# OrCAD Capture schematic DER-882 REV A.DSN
size C; title: DER 882; rev: A
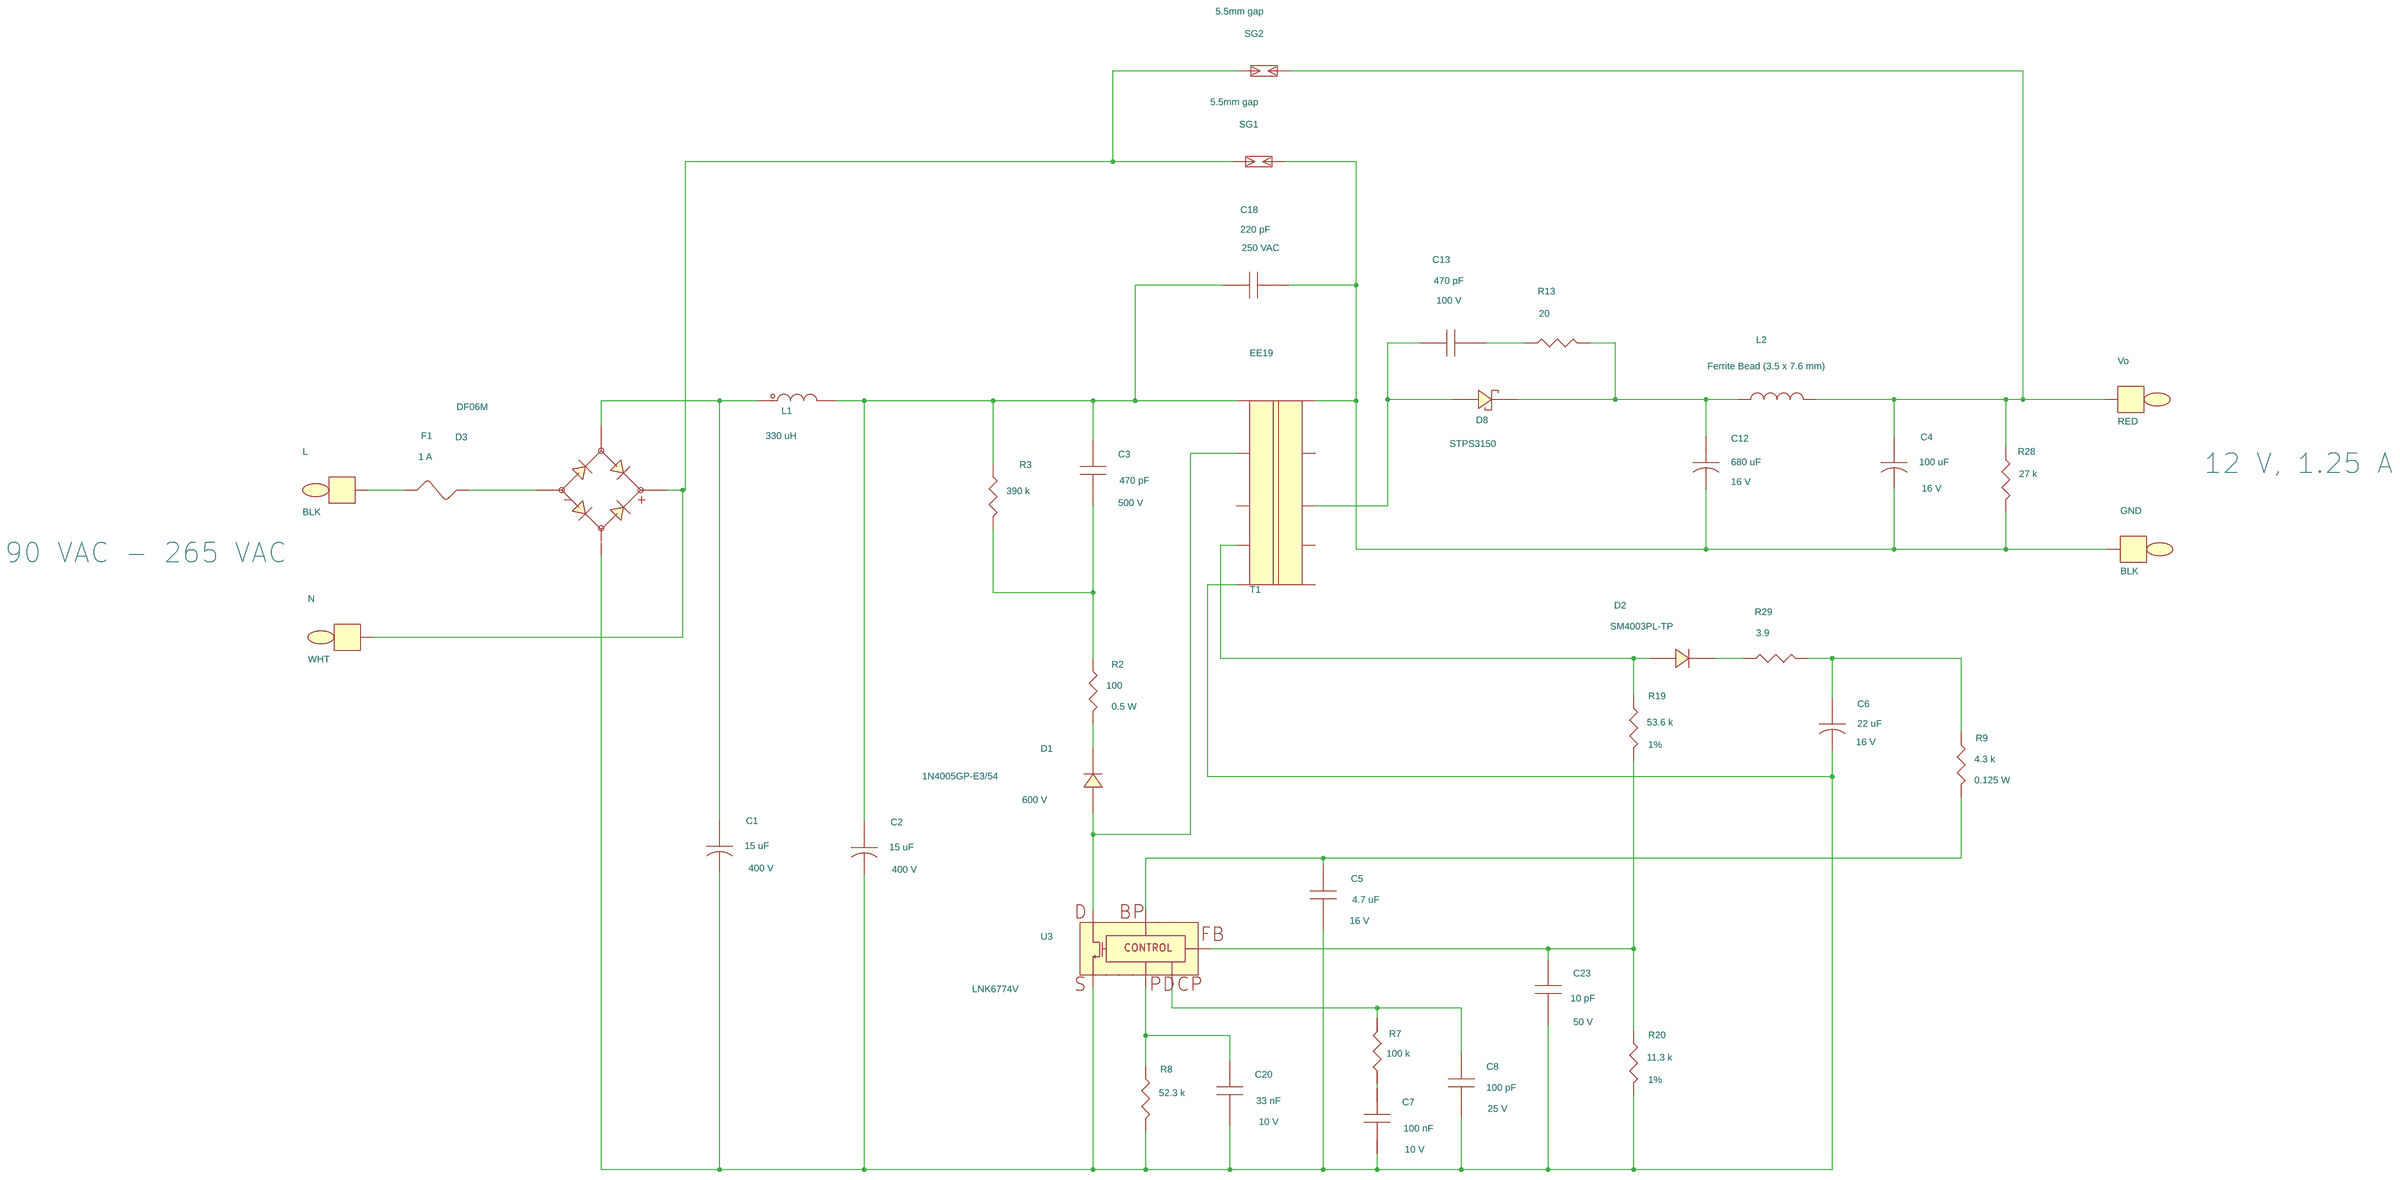
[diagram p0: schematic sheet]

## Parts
C1  15 uF  [pipolcapcyld400ls200040]
C2  15 uF  [pipolcapcyld400ls200040]
C3  470 pF  [pismc1206]
C4  100 uF  [pipolcapcyld250ls100030]
C5  4.7 uF  [pismc0805]
C6  22 uF  [pipolcapclyd200ls80030]
C7  100 nF  [pismc0805]
C8  100 pF  [pismc0805]
C12  680 uF  [pipolcapcyld400ls200040]
C13  470 pF  [pismc0805]
C18  220 pF  [pinpycaprad500x220ls400040]
C20  33 nF  [pismc0805]
C23  10 pF  [pismc0805]
D1  1N4005GP-E3/54  [pidv200x110x040do41]
D2  SM4003PL-TP  [pi_sm_sod-123_12]
D3  DF06M  [pidaxbridgedfm]
D8  STPS3150  [pidv300x200x060do15d0201ad]
F1  1 A  [pi_rst_microfuse]
GND  BLK  [pitpkeystone100x100]
L  BLK  [pitpkeystone125x125]
L1  330 uH  [pi_choke_RL5480-2_d2]
L2  Ferrite Bead (3.5 x 7.6 mm)  [pi12wresd180ls675d040]
N  WHT  [pitpkeystone125x125]
R2  100  [pismr1210]
R3  390 k  [pismr1206]
R7  100 k  [pismr0805]
R8  52.3 k  [pismr0603]
R9  4.3 k  [pi18wvresd80ls100d030]
R13  20  [pismr1206]
R19  53.6 k  [pismr0603]
R20  11.3 k  [pismr0603]
R28  27 k  [pismr1206]
R29  3.9  [pismr0805]
SG1  5.5mm gap  [PI_SPARK_GAP_5p5MM]
SG2  5.5mm gap  [PI_SPARK_GAP_5p5MM]
T1  EE19  [pi_bobbin_ee19_tf-1932_10p]
U3  LNK6774V  [pi_ic_edip_11-12p]
Vo  RED  [pitpkeystone100x100]

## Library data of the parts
C1 C2 = CAP_POL: ALT_SYMBOLS: pipolcapcyld400ls200040800h; Disp_Voltage: 400 V; FPLIST: pipolcapcyld400ls200040,pipolcapcyld400ls200040800h; Part Number: 20-08620-00; Voltage: 400 V
C3 = CAP_NP: ALT_SYMBOLS: pismc1206_1; Disp_Voltage: 500 V; FPLIST: pismc1206,pismc1206_1; Part Number: 20-08965-00; Voltage: 500 V
C4 = CAP_POL: ALT_SYMBOLS: pipolcapcyld250ls100030h; Disp_Voltage: 16 V; FPLIST: pipolcapcyld250ls100030,pipolcapcyld250ls100030h; Part Number: 20-09115-00; Voltage: 16 V
C5 = CAP_NP: Disp_Voltage: 16 V; Part Number: 20-01390-00; Voltage: 16 V
C6 = CAP_POL: ALT_SYMBOLS: pipolcapclyd200ls80030h; Disp_Voltage: 16 V; FPLIST: pipolcapclyd200ls80030,pipolcapclyd200ls80030h; Part Number: 20-00678-00; Voltage: 16 V
C7 = CAP_NP: Disp_Voltage: 10 V; Part Number: 20-01399-00; Voltage: 10 V
C8 = CAP_NP: Disp_Voltage: 25 V; Part Number: 20-09090-00; Voltage: 25 V
C12 = CAP_POL: ALT_SYMBOLS: pipolcapclyd395x630ls200030h; Disp_Voltage: 16 V; FPLIST: pipolcapcyld400ls200040,pipolcapclyd395x630ls200030h; Part Number: 20-00018-00; Voltage: 16 V
C13 = CAP_NP: Disp_Voltage: 100 V; Part Number: 20-00905-00; Voltage: 100 V
C18 = CAP_NP: Disp_Voltage: 250 VAC; Part Number: 20-00379-00; Voltage: 250 VAC
C20 = CAP_NP: Disp_Voltage: 10 V; Part Number: 20-01401-00; Voltage: 10 V
C23 = CAP_NP: Disp_Voltage: 50 V; Part Number: 20-08596-00; Voltage: 50 V
D1 = DIODE: ALT_SYMBOLS: pidv200x110x040do41A,pidax475x125040do41,pidv200x110x040do41wbead,pidax390x125040do41; Disp_Voltage: 600 V; FPLIST: pidv200x110x040do41,pidv200x110x040do41A,pidax475x125040do41,pidv200x110x040do41wbead,pidax390x125040do41; Part Number: 15-01639-00
D2 = DIODE: Part Number: 15-01052-00
D3 = DIODE_BRIDGE_+-~~: Part Number: 15-00367-00
D8 = DIODE_SCHOTTKY: ALT_SYMBOLS: pidax800x225060do15do201ad,pidv300x200x060do14wbead; FPLIST: pidv300x200x060do15d0201ad,pidax800x225060do15do201ad,pidv300x200x060do14wbead; Part Number: 15-00429-00
F1 = FUSE: ALT_SYMBOLS: pirstmicrofusehoz; FPLIST: pi_rst_microfuse,pirstmicrofusehoz; Part Number: 40-00053-00
GND = TESTPOINT: Part Number: 35-00079-00
L = TESTPOINT: Part Number: 35-00042-00
L1 = INDUCTOR_DOT2: ALT_SYMBOLS: pi_choke_RL5480-2H_d2; FPLIST: pi_choke_RL5480-2_d2,pi_choke_RL5480-2H_d2; Part Number: 30-00307-00
L2 = INDUCTOR: ALT_SYMBOLS: pi12wvresd180ls150d040,pi12wvresd180ls200d040,pi12wvresd180ls250d040; FPLIST: pi12wresd180ls675d040,pi12wvresd180ls150d040,pi12wvresd180ls200d040,pi12wvresd180ls250d040; Part Number: 30-00070-00
N = TESTPOINT: Part Number: 35-00044-00
R2 = R: Disp_Power: 0.5 W; Part Number: 05-05428-00
R3 = R: Part Number: 05-01414-00
R7 = R: Part Number: 05-01567-00
R8 = R: Disp_Tol: 1%; Part Number: 05-03253-00
R9 = R: ALT_SYMBOLS: pi18wresd080ls300d030; Disp_Power: 0.125 W; FPLIST: pi18wvresd80ls100d030,pi18wresd080ls300d030; Part Number: 05-02352-00
R13 = R: Part Number: 05-01311-00
R19 = R: Disp_Tol: 1%; Part Number: 05-03254-00
R20 = R: Disp_Tol: 1%; Part Number: 05-03187-00
R28 = R: Part Number: 05-01386-00
R29 = R: Part Number: 05-01461-00
SG1 SG2 = SPARK_GAP: Part Number: 66-00357-00
T1 = BEE19_10P_GENERIC: Part Number: 25-00969-00
U3 = LNKHP_eDIP_eSOP: Part Number: 10-00429-00
Vo = TESTPOINT: Part Number: 35-00080-00

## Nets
SOURCE: U3.8(SOURCE) U3.9(SOURCE) U3.10(SOURCE) U3.11(SOURCE) U3.12(SOURCE)
N00259: D3.1 N.1 SG1.1 SG2.1
N00630: C1.1 D3.4 L1.2
N00726: C2.1 C3.1 C18.1 L1.1 R3.1 T1.5
N00888: C1.2 C2.2 C5.2 C6.2 C7.2 C8.2 C20.2 C23.2 D3.3 R8.2 R20.2 T1.1 U3.7(S7)
N01419: C3.2 R2.1 R3.2
N01721: D1.1 R2.2
N01734: D1.2 T1.4 U3.6(D)
N02114: C20.1 R8.1 U3.1(PD)
N02454: C8.1 R7.2 U3.3(CP)
N02521: C7.1 R7.1
N02815: C23.1 R19.2 R20.1 U3.2(FB)
N03133: D2.2 R19.1 T1.2
N03607: C6.1 R9.1 R29.2
N03667: C5.1 R9.2 U3.4(BP)
N04837: C12.1 D8.1 L2.1 R13.2
N04849: C13.1 D8.2 T1.8
N05156: C4.1 L2.2 R28.1 SG2.2 Vo.1
N05219: C4.2 C12.2 C18.2 GND.1 R28.2 SG1.2 T1.6
N08385: D3.2 F1.2
N14611: C13.2 R13.1
N4395058: D2.1 R29.1
N4400229: F1.1 L.1

Not connected (* = marked no-connect by the designer): T1 3 7 9 10

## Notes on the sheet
- 12 V, 1.25 A
- 90 VAC - 265 VAC
